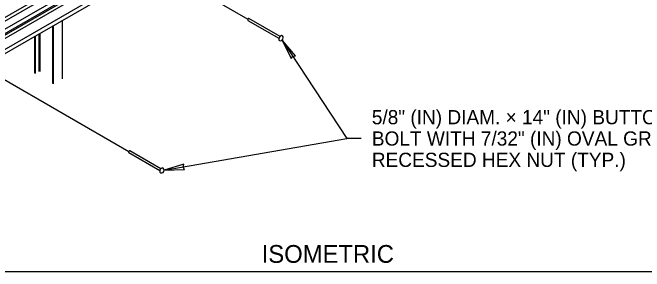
# Model space of a CAD drawing. Extents: x 99862 to 103680, y 99470 to 102076.
# Drawn here: x 101380 to 102089, y 100000 to 100291 of the extents above; entities that cross this region are included whole.
import ezdxf

# ---------------------------------------------------------------- set-up
doc = ezdxf.new("R2010")
doc.units = 0
for name, color, linetype in [('Level 1', 7, 'Continuous'), ('Level 14', 7, 'Continuous'), ('Level 15', 7, 'Continuous'), ('Level 20', 7, 'Continuous'), ('Level 27', 7, 'Continuous'), ('Level 4', 7, 'Continuous'), ('Level 7', 7, 'Continuous')]:
    doc.layers.add(name, color=color, linetype=linetype)

msp = doc.modelspace()

# ---------------------------------------------------------------- linework, layer by layer
at = {"layer": 'Level 1'}
msp.add_lwpolyline([(99862, 99999.5), (103151, 99999.5), (103151, 102075.5), (99862, 102075.5)], close=True, dxfattribs=at)
at = {"layer": 'Level 14'}
for p, q in [((101521.29, 100354.02), (101643.88, 100283.24)), ((101326.35, 100240.57), (101510.09, 100134.48))]:
    msp.add_line(p, q, dxfattribs=at)
at = {"layer": 'Level 15'}
for p in [(101682.31, 100259.63), (101549.78, 100113.43), (101771.05, 100148.98)]:
    msp.add_line(p, (101755.05, 100148.98), dxfattribs=at)
for points in [[(101682.31, 100259.63), (101692.36, 100238.92), (101694.27, 100241.44), (101697.35, 100242.19)], [(101549.78, 100113.43), (101572.79, 100114.11), (101571.28, 100116.89), (101571.84, 100120.01)]]:
    msp.add_lwpolyline(points, close=True, dxfattribs=at)
at = {"layer": 'Level 27'}
for p, q in [((101640.62, 100440.82), (101218.47, 100197.09)), ((101643.47, 100438.49), (101253.92, 100213.58)), ((101648.24, 100432.03), (101258.68, 100207.12)), ((101251.35, 100198.17), (101648.6, 100427.52)), ((101641.94, 100418.14), (101252.39, 100193.23)), ((101648.26, 100409.4), (101258.71, 100184.49)), ((101259.04, 100180.02), (101648.59, 100404.93)), ((101525.5, 100354.41), (101251.35, 100196.12)), ((101409.44, 100224.51), (101409.44, 100266.86)), ((101410.74, 100224.51), (101410.74, 100267.61))]:
    msp.add_line(p, q, dxfattribs=at)
at = {"layer": 'Level 4'}
for p, q in [((101435.66, 100216.29), (101435.66, 100281.99)), ((101424.86, 100210.7), (101424.86, 100275.76)), ((101425.42, 100210.38), (101425.42, 100276.08)), ((101404.64, 100222.38), (101404.64, 100264.08)), ((101405.2, 100222.05), (101405.2, 100264.4))]:
    msp.add_line(p, q, dxfattribs=at)
at = {"layer": 'Level 7'}
for p, q in [((101643.88, 100281.91), (101678.79, 100261.76)), ((101679.93, 100263.75), (101645.03, 100283.9)), ((101510.09, 100133.15), (101544.99, 100113)), ((101546.14, 100114.99), (101511.24, 100135.14))]:
    msp.add_line(p, q, dxfattribs=at)
for centre, start, end in [((101680.34, 100262.19), 255.16984, 360), ((101680.34, 100262.19), 360, 44.83016), ((101546.55, 100113.43), 255.16984, 360), ((101546.55, 100113.43), 360, 44.83016)]:
    msp.add_arc(centre, 3.23, start, end, dxfattribs=at)
for centre, major_axis, start_param, end_param in [((101644.46, 100282.91), (0.574, 0.994), 6.283185, 9.424778), ((101680.83, 100261.91), (1.58, 2.73), 6.127909, 9.580054), ((101510.66, 100134.15), (0.574, 0.994), 6.283185, 9.424778), ((101547.04, 100113.15), (1.58, 2.73), 6.127909, 9.580054)]:
    msp.add_ellipse(centre, major_axis=major_axis, ratio=0.57735, start_param=start_param, end_param=end_param, dxfattribs=at)

# ---------------------------------------------------------------- texts
at = {"layer": 'Level 20'}
for s, height, p in [('5/8" (IN) DIAM. × 14" (IN) BUTTON HEAD', 16, (101783.05, 100164.99)), ('BOLT WITH 7/32" (IN) OVAL GRIP AND', 16, (101783.05, 100140.99)), ('RECESSED HEX NUT (TYP.)', 16, (101783.05, 100116.99)), ('ISOMETRIC ', 20, (101659.35, 100009.13))]:
    msp.add_text(s, height=height, dxfattribs=at).set_placement(p)

doc.saveas('drawing.dxf')
